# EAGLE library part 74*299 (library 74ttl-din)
8-bit universal SHIFT/STORAGE REGISTER
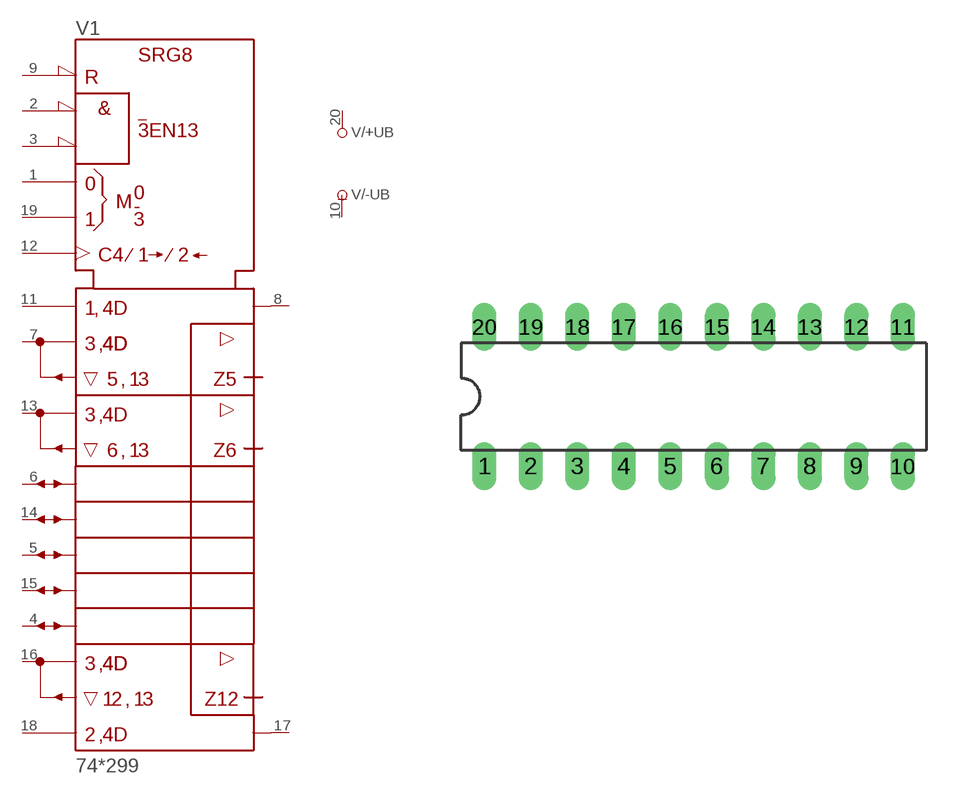
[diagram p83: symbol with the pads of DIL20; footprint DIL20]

Designator prefix V; gates /+UB=+UB /-UB=-UB 1=299

## 74299N  [DIL20]
1  1:S0  in
2  1:G\1  in
3  1:G\2  in
4  1:G/QG  in
5  1:E/QE  in
6  1:C/QC  in
7  1:A/QA  in
8  1:QA*  out
9  1:CLR\  in
10  /-UB:-UB  pwr
11  1:SR  in
12  1:CLK  out
13  1:B/QB  in
14  1:D/QD  in
15  1:F/QF  in
16  1:H/QH  in
17  1:QH*  out
18  1:SL  in
19  1:S1  in
20  /+UB:+UB  pwr

## Footprint DIL20 (pad centres in mm)
Dual In Line Package
drill 0.813 long: 1 -11.43,-3.81; 2 -8.89,-3.81; 3 -6.35,-3.81; 4 -3.81,-3.81; 5 -1.27,-3.81; 6 1.27,-3.81; 7 3.81,-3.81; 8 6.35,-3.81; 9 8.89,-3.81; 10 11.43,-3.81; 11 11.43,3.81; 12 8.89,3.81; 13 6.35,3.81; 14 3.81,3.81; 15 1.27,3.81; 16 -1.27,3.81; 17 -3.81,3.81; 18 -6.35,3.81; 19 -8.89,3.81; 20 -11.43,3.81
